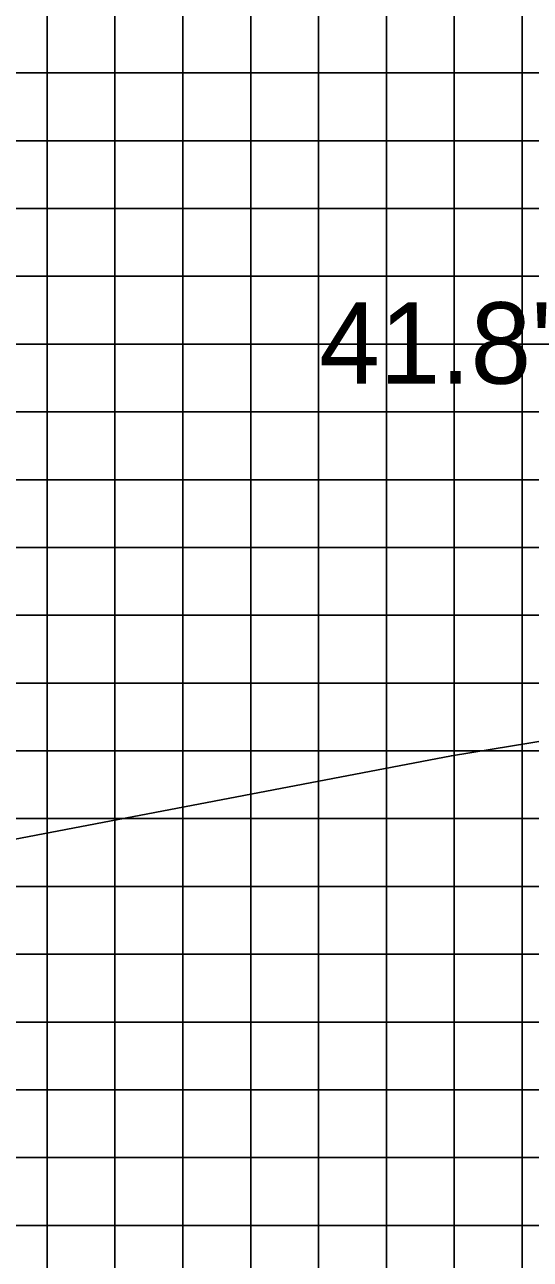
# Model space of a CAD drawing. Extents: x 1782647 to 1782990, y 442591 to 442811.
# Drawn here: x 1782763.62 to 1782771.07, y 442623.17 to 442641.38 of the extents above; entities that cross this region are included whole.
import ezdxf

# ---------------------------------------------------------------- set-up
doc = ezdxf.new("R2010")
doc.units = 0
for name, color, linetype in [('D_Text_Standard', 7, 'Continuous'), ('MAJOR', 7, 'Continuous'), ('MINOR', 7, 'Continuous'), ('S_Roadway_Centerline', 7, 'Continuous')]:
    doc.layers.add(name, color=color, linetype=linetype)

msp = doc.modelspace()

# ---------------------------------------------------------------- linework, layer by layer
at = {"layer": 'MAJOR'}
for p, q in [((1782672.947, 442638.665), (1782952.947, 442638.665)), ((1782672.947, 442633.665), (1782952.947, 442633.665)), ((1782672.947, 442628.665), (1782952.947, 442628.665)), ((1782672.947, 442623.665), (1782952.947, 442623.665))]:
    msp.add_line(p, q, dxfattribs=at)
at = {"layer": 'MINOR'}
for p, q in [((1782763.947, 442608.665), (1782763.947, 442653.665)), ((1782764.947, 442608.665), (1782764.947, 442653.665)), ((1782765.947, 442608.665), (1782765.947, 442653.665)), ((1782766.947, 442608.665), (1782766.947, 442653.665)), ((1782767.947, 442608.665), (1782767.947, 442653.665)), ((1782768.947, 442608.665), (1782768.947, 442653.665)), ((1782769.947, 442608.665), (1782769.947, 442653.665)), ((1782770.947, 442608.665), (1782770.947, 442653.665)), ((1782672.947, 442640.665), (1782952.947, 442640.665)), ((1782672.947, 442639.665), (1782952.947, 442639.665)), ((1782672.947, 442637.665), (1782952.947, 442637.665)), ((1782672.947, 442636.665), (1782952.947, 442636.665)), ((1782672.947, 442635.665), (1782952.947, 442635.665)), ((1782672.947, 442634.665), (1782952.947, 442634.665)), ((1782672.947, 442632.665), (1782952.947, 442632.665)), ((1782672.947, 442631.665), (1782952.947, 442631.665)), ((1782672.947, 442630.665), (1782952.947, 442630.665)), ((1782672.947, 442629.665), (1782952.947, 442629.665)), ((1782672.947, 442627.665), (1782952.947, 442627.665)), ((1782672.947, 442626.665), (1782952.947, 442626.665)), ((1782672.947, 442625.665), (1782952.947, 442625.665)), ((1782672.947, 442624.665), (1782952.947, 442624.665))]:
    msp.add_line(p, q, dxfattribs=at)
at = {"layer": 'S_Roadway_Centerline'}
msp.add_lwpolyline([(1782759.409, 442628.584), (1782769.904, 442630.592), (1782771.644, 442630.875), (1782773.198, 442631.131), (1782791.798, 442632.903), (1782797.041, 442633.325), (1782806.857, 442633.739), (1782816.845, 442634.722), (1782817.791, 442634.815), (1782818.812, 442634.918), (1782829.734, 442635.795), (1782841.885, 442636.625), (1782842.013, 442636.634), (1782842.143, 442636.643), (1782863.277, 442638.125), (1782865.446, 442638.297), (1782875.481, 442638.98), (1782886.179, 442639.988), (1782898.169, 442641.087)], dxfattribs=at)

# ---------------------------------------------------------------- texts
at = {"layer": 'D_Text_Standard'}
msp.add_text("41.8'", height=1.2, dxfattribs=at).set_placement((1782767.956, 442636.081))

doc.saveas('drawing.dxf')
